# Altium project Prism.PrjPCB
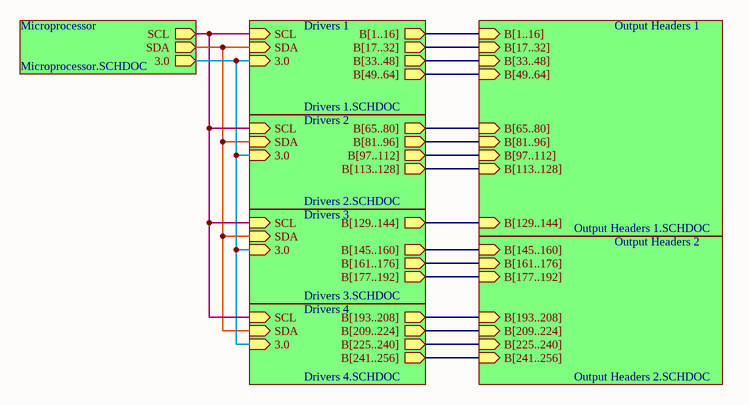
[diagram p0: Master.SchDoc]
8 sheets, 82 parts. Net scope: hierarchical (ports join the sheet entries above them; power ports are global).
Board file: Micro Board.PCBDoc
Sheets:
  Master.SchDoc
    Output Headers 2 = Output Headers 2.SchDoc
    Output Headers 1 = Output Headers 1.SchDoc
    Microprocessor = Microprocessor.SchDoc
    Drivers 1 = Drivers 1.SchDoc
    Drivers 2 = Drivers 2.SchDoc
    Drivers 3 = Drivers 3.SchDoc
    Drivers 4 = Drivers 4.SchDoc

## Sheet Master.SchDoc: Master
size A; DocumentNumber: 1; SheetNumber: 1

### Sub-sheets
Drivers 1 = Drivers 1.SCHDOC: B[1..16] (out), B[17..32] (out), B[33..48] (out), B[49..64] (out), SCL (in), SDA (in), 3.0 (in)
Drivers 2 = Drivers 2.SCHDOC: B[97..112] (out), B[113..128] (out), B[65..80] (out), B[81..96] (out), SCL (in), SDA (in), 3.0 (in)
Drivers 3 = Drivers 3.SCHDOC: B[161..176] (out), B[177..192] (out), B[129..144] (out), B[145..160] (out), SCL (in), SDA (in), 3.0 (in)
Drivers 4 = Drivers 4.SCHDOC: B[241..256] (out), B[193..208] (out), B[209..224] (out), B[225..240] (out), SCL (in), SDA (in), 3.0 (in)
Microprocessor = Microprocessor.SCHDOC: SDA (out), SCL (out), 3.0 (out)
Output Headers 1 = Output Headers 1.SCHDOC: B[1..16] (in), B[17..32] (in), B[33..48] (in), B[81..96] (in), B[65..80] (in), B[49..64] (in), B[97..112] (in), B[113..128] (in), B[129..144] (in)
Output Headers 2 = Output Headers 2.SCHDOC: B[177..192] (in), B[161..176] (in), B[145..160] (in), B[193..208] (in), B[209..224] (in), B[225..240] (in), B[241..256] (in)

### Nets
NetC1_1: sheet Microprocessor/3.0, sheet Drivers 1/3.0, sheet Drivers 2/3.0, sheet Drivers 3/3.0, sheet Drivers 4/3.0
NetR33_1: sheet Microprocessor/SDA, sheet Drivers 1/SDA, sheet Drivers 2/SDA, sheet Drivers 3/SDA, sheet Drivers 4/SDA
NetR34_1: sheet Microprocessor/SCL, sheet Drivers 1/SCL, sheet Drivers 2/SCL, sheet Drivers 3/SCL, sheet Drivers 4/SCL

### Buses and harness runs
bus sheet Drivers 1/B[1..16] = sheet Output Headers 1/B[1..16]
bus sheet Drivers 1/B[17..32] = sheet Output Headers 1/B[17..32]
bus sheet Drivers 1/B[33..48] = sheet Output Headers 1/B[33..48]
bus sheet Drivers 1/B[49..64] = sheet Output Headers 1/B[49..64]
bus sheet Drivers 2/B[65..80] = sheet Output Headers 1/B[65..80]
bus sheet Drivers 2/B[81..96] = sheet Output Headers 1/B[81..96]
bus sheet Drivers 2/B[97..112] = sheet Output Headers 1/B[97..112]
bus sheet Drivers 2/B[113..128] = sheet Output Headers 1/B[113..128]
bus sheet Drivers 3/B[129..144] = sheet Output Headers 1/B[129..144]
bus sheet Drivers 3/B[145..160] = sheet Output Headers 2/B[145..160]
bus sheet Drivers 3/B[161..176] = sheet Output Headers 2/B[161..176]
bus sheet Drivers 3/B[177..192] = sheet Output Headers 2/B[177..192]
bus sheet Drivers 4/B[193..208] = sheet Output Headers 2/B[193..208]
bus sheet Drivers 4/B[209..224] = sheet Output Headers 2/B[209..224]
bus sheet Drivers 4/B[225..240] = sheet Output Headers 2/B[225..240]
bus sheet Drivers 4/B[241..256] = sheet Output Headers 2/B[241..256]

## Sheet Output Headers 2.SchDoc: Output Header Connections 2
size A; DocumentNumber: 1; SheetNumber: 7
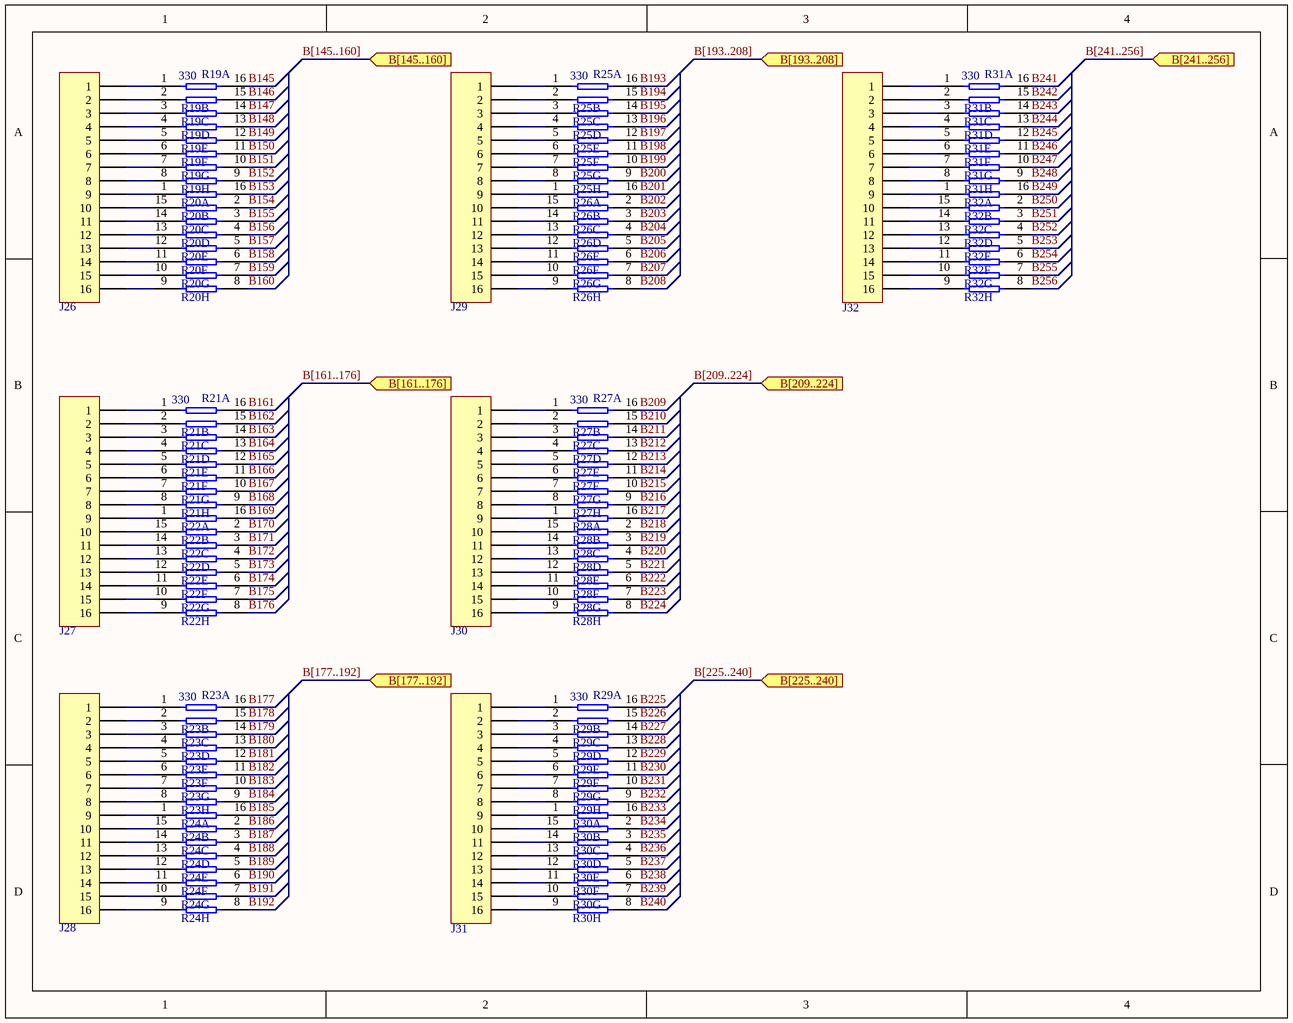
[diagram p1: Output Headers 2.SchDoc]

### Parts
J26  HDR2X8  [HDR2X8]  (value not drawn)
J27  HDR2X8  [HDR2X8]  (value not drawn)
J28  HDR2X8  [HDR2X8]  (value not drawn)
J29  HDR2X8  [HDR2X8]  (value not drawn)
J30  HDR2X8  [HDR2X8]  (value not drawn)
J31  HDR2X8  [HDR2X8]  (value not drawn)
J32  HDR2X8  [HDR2X8]  (value not drawn)
R19  330  [DIP-16]  (parts A,B,C,D,E,F,G,H of 8)
R20  330  [DIP-16]  (value not drawn)  (parts A,B,C,D,E,F,G,H of 8)
R21  330  [DIP-16]  (parts A,B,C,D,E,F,G,H of 8)
R22  330  [DIP-16]  (value not drawn)  (parts A,B,C,D,E,F,G,H of 8)
R23  330  [DIP-16]  (parts A,B,C,D,E,F,G,H of 8)
R24  330  [DIP-16]  (value not drawn)  (parts A,B,C,D,E,F,G,H of 8)
R25  330  [DIP-16]  (parts A,B,C,D,E,F,G,H of 8)
R26  330  [DIP-16]  (value not drawn)  (parts A,B,C,D,E,F,G,H of 8)
R27  330  [DIP-16]  (parts A,B,C,D,E,F,G,H of 8)
R28  330  [DIP-16]  (value not drawn)  (parts A,B,C,D,E,F,G,H of 8)
R29  330  [DIP-16]  (parts A,B,C,D,E,F,G,H of 8)
R30  330  [DIP-16]  (value not drawn)  (parts A,B,C,D,E,F,G,H of 8)
R31  330  [DIP-16]  (parts A,B,C,D,E,F,G,H of 8)
R32  330  [DIP-16]  (value not drawn)  (parts A,B,C,D,E,F,G,H of 8)

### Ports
B[145..160] (in), B[161..176] (in), B[177..192] (in), B[193..208] (in), B[209..224] (in), B[225..240] (in), B[241..256] (in)

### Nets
B145: R19.16
B146: R19.15
B147: R19.14
B148: R19.13
B149: R19.12
B150: R19.11
B151: R19.10
B152: R19.9
B153: R20.16
B154: R20.2
B155: R20.3
B156: R20.4
B157: R20.5
B158: R20.6
B159: R20.7
B160: R20.8
B161: R21.16
B162: R21.15
B163: R21.14
B164: R21.13
B165: R21.12
B166: R21.11
B167: R21.10
B168: R21.9
B169: R22.16
B170: R22.2
B171: R22.3
B172: R22.4
B173: R22.5
B174: R22.6
B175: R22.7
B176: R22.8
B177: R23.16
B178: R23.15
B179: R23.14
B180: R23.13
B181: R23.12
B182: R23.11
B183: R23.10
B184: R23.9
B185: R24.16
B186: R24.2
B187: R24.3
B188: R24.4
B189: R24.5
B190: R24.6
B191: R24.7
B192: R24.8
B193: R25.16
B194: R25.15
B195: R25.14
B196: R25.13
B197: R25.12
B198: R25.11
B199: R25.10
B200: R25.9
B201: R26.16
B202: R26.2
B203: R26.3
B204: R26.4
B205: R26.5
B206: R26.6
B207: R26.7
B208: R26.8
B209: R27.16
B210: R27.15
B211: R27.14
B212: R27.13
B213: R27.12
B214: R27.11
B215: R27.10
B216: R27.9
B217: R28.16
B218: R28.2
B219: R28.3
B220: R28.4
B221: R28.5
B222: R28.6
B223: R28.7
B224: R28.8
B225: R29.16
B226: R29.15
B227: R29.14
B228: R29.13
B229: R29.12
B230: R29.11
B231: R29.10
B232: R29.9
B233: R30.16
B234: R30.2
B235: R30.3
B236: R30.4
B237: R30.5
B238: R30.6
B239: R30.7
B240: R30.8
B241: R31.16
B242: R31.15
B243: R31.14
B244: R31.13
B245: R31.12
B246: R31.11
B247: R31.10
B248: R31.9
B249: R32.16
B250: R32.2
B251: R32.3
B252: R32.4
B253: R32.5
B254: R32.6
B255: R32.7
B256: R32.8
NetJ26_1: J26.1 R19.1
NetJ26_2: J26.2 R19.2
NetJ26_3: J26.3 R19.3
NetJ26_4: J26.4 R19.4
NetJ26_5: J26.5 R19.5
NetJ26_6: J26.6 R19.6
NetJ26_7: J26.7 R19.7
NetJ26_8: J26.8 R19.8
NetJ26_9: J26.9 R20.1
NetJ26_10: J26.10 R20.15
NetJ26_11: J26.11 R20.14
NetJ26_12: J26.12 R20.13
NetJ26_13: J26.13 R20.12
NetJ26_14: J26.14 R20.11
NetJ26_15: J26.15 R20.10
NetJ26_16: J26.16 R20.9
NetJ27_1: J27.1 R21.1
NetJ27_2: J27.2 R21.2
NetJ27_3: J27.3 R21.3
NetJ27_4: J27.4 R21.4
NetJ27_5: J27.5 R21.5
NetJ27_6: J27.6 R21.6
NetJ27_7: J27.7 R21.7
NetJ27_8: J27.8 R21.8
NetJ27_9: J27.9 R22.1
NetJ27_10: J27.10 R22.15
NetJ27_11: J27.11 R22.14
NetJ27_12: J27.12 R22.13
NetJ27_13: J27.13 R22.12
NetJ27_14: J27.14 R22.11
NetJ27_15: J27.15 R22.10
NetJ27_16: J27.16 R22.9
NetJ28_1: J28.1 R23.1
NetJ28_2: J28.2 R23.2
NetJ28_3: J28.3 R23.3
NetJ28_4: J28.4 R23.4
NetJ28_5: J28.5 R23.5
NetJ28_6: J28.6 R23.6
NetJ28_7: J28.7 R23.7
NetJ28_8: J28.8 R23.8
NetJ28_9: J28.9 R24.1
NetJ28_10: J28.10 R24.15
NetJ28_11: J28.11 R24.14
NetJ28_12: J28.12 R24.13
NetJ28_13: J28.13 R24.12
NetJ28_14: J28.14 R24.11
NetJ28_15: J28.15 R24.10
NetJ28_16: J28.16 R24.9
NetJ29_1: J29.1 R25.1
NetJ29_2: J29.2 R25.2
NetJ29_3: J29.3 R25.3
NetJ29_4: J29.4 R25.4
NetJ29_5: J29.5 R25.5
NetJ29_6: J29.6 R25.6
NetJ29_7: J29.7 R25.7
NetJ29_8: J29.8 R25.8
NetJ29_9: J29.9 R26.1
NetJ29_10: J29.10 R26.15
NetJ29_11: J29.11 R26.14
NetJ29_12: J29.12 R26.13
NetJ29_13: J29.13 R26.12
NetJ29_14: J29.14 R26.11
NetJ29_15: J29.15 R26.10
NetJ29_16: J29.16 R26.9
NetJ30_1: J30.1 R27.1
NetJ30_2: J30.2 R27.2
NetJ30_3: J30.3 R27.3
NetJ30_4: J30.4 R27.4
NetJ30_5: J30.5 R27.5
NetJ30_6: J30.6 R27.6
NetJ30_7: J30.7 R27.7
NetJ30_8: J30.8 R27.8
NetJ30_9: J30.9 R28.1
NetJ30_10: J30.10 R28.15
NetJ30_11: J30.11 R28.14
NetJ30_12: J30.12 R28.13
NetJ30_13: J30.13 R28.12
NetJ30_14: J30.14 R28.11
NetJ30_15: J30.15 R28.10
NetJ30_16: J30.16 R28.9
NetJ31_1: J31.1 R29.1
NetJ31_2: J31.2 R29.2
NetJ31_3: J31.3 R29.3
NetJ31_4: J31.4 R29.4
NetJ31_5: J31.5 R29.5
NetJ31_6: J31.6 R29.6
NetJ31_7: J31.7 R29.7
NetJ31_8: J31.8 R29.8
NetJ31_9: J31.9 R30.1
NetJ31_10: J31.10 R30.15
NetJ31_11: J31.11 R30.14
NetJ31_12: J31.12 R30.13
NetJ31_13: J31.13 R30.12
NetJ31_14: J31.14 R30.11
NetJ31_15: J31.15 R30.10
NetJ31_16: J31.16 R30.9
NetJ32_1: J32.1 R31.1
NetJ32_2: J32.2 R31.2
NetJ32_3: J32.3 R31.3
NetJ32_4: J32.4 R31.4
NetJ32_5: J32.5 R31.5
NetJ32_6: J32.6 R31.6
NetJ32_7: J32.7 R31.7
NetJ32_8: J32.8 R31.8
NetJ32_9: J32.9 R32.1
NetJ32_10: J32.10 R32.15
NetJ32_11: J32.11 R32.14
NetJ32_12: J32.12 R32.13
NetJ32_13: J32.13 R32.12
NetJ32_14: J32.14 R32.11
NetJ32_15: J32.15 R32.10
NetJ32_16: J32.16 R32.9

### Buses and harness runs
bus B[145..160] = port B[145..160]
bus B[161..176] = port B[161..176]
bus B[177..192] = port B[177..192]
bus B[193..208] = port B[193..208]
bus B[209..224] = port B[209..224]
bus B[225..240] = port B[225..240]
bus B[241..256] = port B[241..256]

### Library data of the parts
J26-J32 = MHDR1X16: Header, 16-Pin; Manufacturer: Generic Components; Class I: Connector
R19-R32 = Res Pack2: Resistor Array - Parts; Manufacturer: Generic Components; Class I: Passive; Value: 1K

## Sheet Output Headers 1.SchDoc: Output Headers
size A; DocumentNumber: 1; SheetNumber: 6
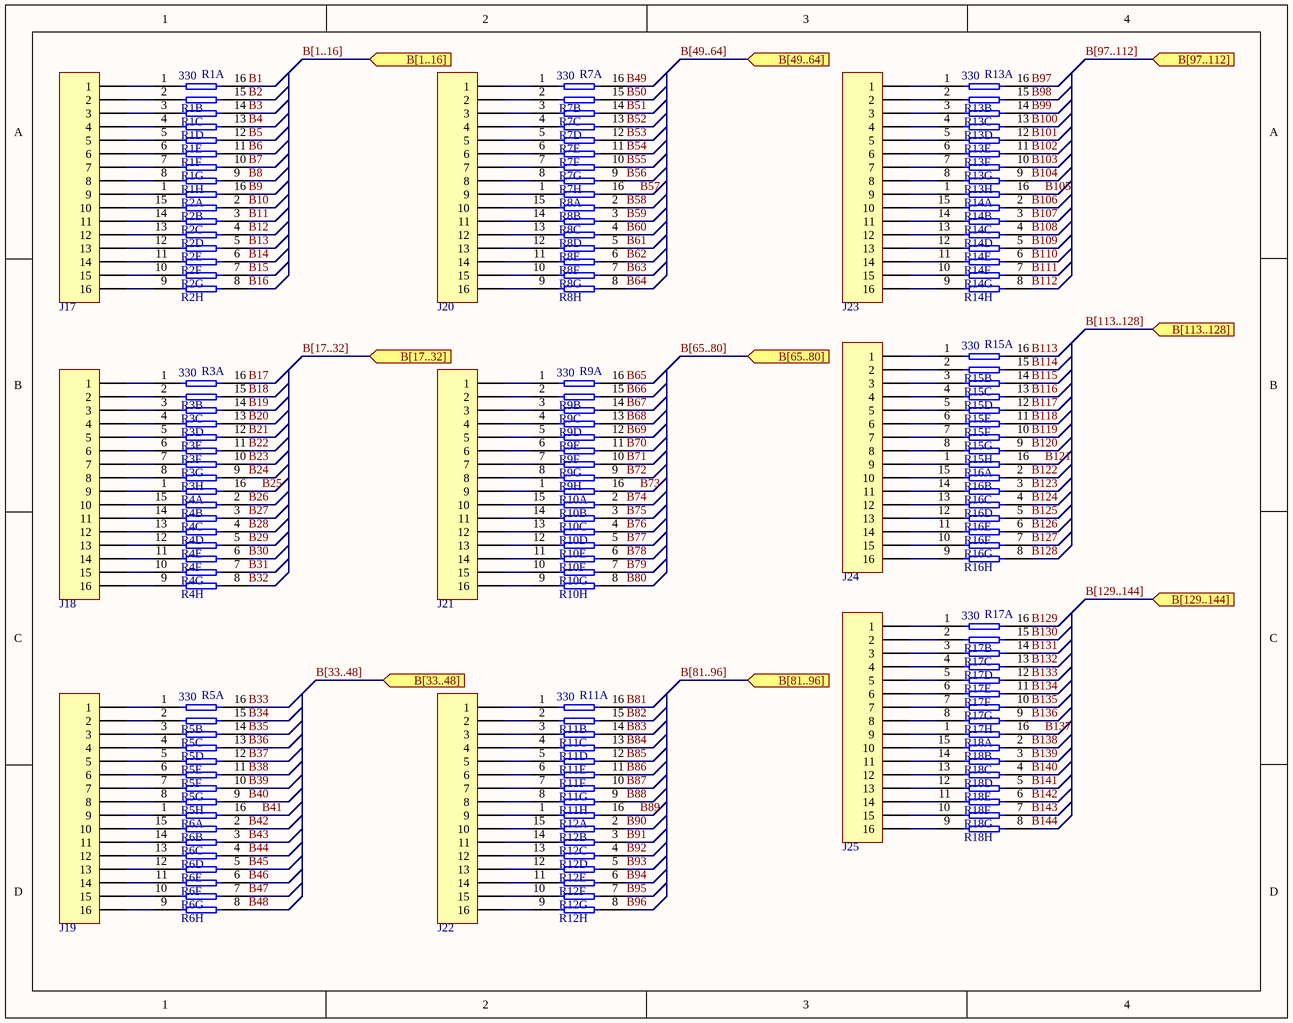
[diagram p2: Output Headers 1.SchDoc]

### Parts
J17  HDR2X8  [HDR2X8]  (value not drawn)
J18  HDR2X8  [HDR2X8]  (value not drawn)
J19  HDR2X8  [HDR2X8]  (value not drawn)
J20  HDR2X8  [HDR2X8]  (value not drawn)
J21  HDR2X8  [HDR2X8]  (value not drawn)
J22  HDR2X8  [HDR2X8]  (value not drawn)
J23  HDR2X8  [HDR2X8]  (value not drawn)
J24  HDR2X8  [HDR2X8]  (value not drawn)
J25  HDR2X8  [HDR2X8]  (value not drawn)
R1  330  [DIP-16]  (parts A,B,C,D,E,F,G,H of 8)
R2  330  [DIP-16]  (value not drawn)  (parts A,B,C,D,E,F,G,H of 8)
R3  330  [DIP-16]  (parts A,B,C,D,E,F,G,H of 8)
R4  330  [DIP-16]  (value not drawn)  (parts A,B,C,D,E,F,G,H of 8)
R5  330  [DIP-16]  (parts A,B,C,D,E,F,G,H of 8)
R6  330  [DIP-16]  (value not drawn)  (parts A,B,C,D,E,F,G,H of 8)
R7  330  [DIP-16]  (parts A,B,C,D,E,F,G,H of 8)
R8  330  [DIP-16]  (value not drawn)  (parts A,B,C,D,E,F,G,H of 8)
R9  330  [DIP-16]  (parts A,B,C,D,E,F,G,H of 8)
R10  330  [DIP-16]  (value not drawn)  (parts A,B,C,D,E,F,G,H of 8)
R11  330  [DIP-16]  (parts A,B,C,D,E,F,G,H of 8)
R12  330  [DIP-16]  (value not drawn)  (parts A,B,C,D,E,F,G,H of 8)
R13  330  [DIP-16]  (parts A,B,C,D,E,F,G,H of 8)
R14  330  [DIP-16]  (value not drawn)  (parts A,B,C,D,E,F,G,H of 8)
R15  330  [DIP-16]  (parts A,B,C,D,E,F,G,H of 8)
R16  330  [DIP-16]  (value not drawn)  (parts A,B,C,D,E,F,G,H of 8)
R17  330  [DIP-16]  (parts A,B,C,D,E,F,G,H of 8)
R18  330  [DIP-16]  (value not drawn)  (parts A,B,C,D,E,F,G,H of 8)

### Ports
B[1..16] (in), B[17..32] (in), B[33..48] (in), B[49..64] (in), B[65..80] (in), B[81..96] (in), B[97..112] (in), B[113..128] (in), B[129..144] (in)

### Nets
B1: R1.16
B2: R1.15
B3: R1.14
B4: R1.13
B5: R1.12
B6: R1.11
B7: R1.10
B8: R1.9
B9: R2.16
B10: R2.2
B11: R2.3
B12: R2.4
B13: R2.5
B14: R2.6
B15: R2.7
B16: R2.8
B17: R3.16
B18: R3.15
B19: R3.14
B20: R3.13
B21: R3.12
B22: R3.11
B23: R3.10
B24: R3.9
B25: R4.16
B26: R4.2
B27: R4.3
B28: R4.4
B29: R4.5
B30: R4.6
B31: R4.7
B32: R4.8
B33: R5.16
B34: R5.15
B35: R5.14
B36: R5.13
B37: R5.12
B38: R5.11
B39: R5.10
B40: R5.9
B41: R6.16
B42: R6.2
B43: R6.3
B44: R6.4
B45: R6.5
B46: R6.6
B47: R6.7
B48: R6.8
B49: R7.16
B50: R7.15
B51: R7.14
B52: R7.13
B53: R7.12
B54: R7.11
B55: R7.10
B56: R7.9
B57: R8.16
B58: R8.2
B59: R8.3
B60: R8.4
B61: R8.5
B62: R8.6
B63: R8.7
B64: R8.8
B65: R9.16
B66: R9.15
B67: R9.14
B68: R9.13
B69: R9.12
B70: R9.11
B71: R9.10
B72: R9.9
B73: R10.16
B74: R10.2
B75: R10.3
B76: R10.4
B77: R10.5
B78: R10.6
B79: R10.7
B80: R10.8
B81: R11.16
B82: R11.15
B83: R11.14
B84: R11.13
B85: R11.12
B86: R11.11
B87: R11.10
B88: R11.9
B89: R12.16
B90: R12.2
B91: R12.3
B92: R12.4
B93: R12.5
B94: R12.6
B95: R12.7
B96: R12.8
B97: R13.16
B98: R13.15
B99: R13.14
B100: R13.13
B101: R13.12
B102: R13.11
B103: R13.10
B104: R13.9
B105: R14.16
B106: R14.2
B107: R14.3
B108: R14.4
B109: R14.5
B110: R14.6
B111: R14.7
B112: R14.8
B113: R15.16
B114: R15.15
B115: R15.14
B116: R15.13
B117: R15.12
B118: R15.11
B119: R15.10
B120: R15.9
B121: R16.16
B122: R16.2
B123: R16.3
B124: R16.4
B125: R16.5
B126: R16.6
B127: R16.7
B128: R16.8
B129: R17.16
B130: R17.15
B131: R17.14
B132: R17.13
B133: R17.12
B134: R17.11
B135: R17.10
B136: R17.9
B137: R18.16
B138: R18.2
B139: R18.3
B140: R18.4
B141: R18.5
B142: R18.6
B143: R18.7
B144: R18.8
NetJ17_1: J17.1 R1.1
NetJ17_2: J17.2 R1.2
NetJ17_3: J17.3 R1.3
NetJ17_4: J17.4 R1.4
NetJ17_5: J17.5 R1.5
NetJ17_6: J17.6 R1.6
NetJ17_7: J17.7 R1.7
NetJ17_8: J17.8 R1.8
NetJ17_9: J17.9 R2.1
NetJ17_10: J17.10 R2.15
NetJ17_11: J17.11 R2.14
NetJ17_12: J17.12 R2.13
NetJ17_13: J17.13 R2.12
NetJ17_14: J17.14 R2.11
NetJ17_15: J17.15 R2.10
NetJ17_16: J17.16 R2.9
NetJ18_1: J18.1 R3.1
NetJ18_2: J18.2 R3.2
NetJ18_3: J18.3 R3.3
NetJ18_4: J18.4 R3.4
NetJ18_5: J18.5 R3.5
NetJ18_6: J18.6 R3.6
NetJ18_7: J18.7 R3.7
NetJ18_8: J18.8 R3.8
NetJ18_9: J18.9 R4.1
NetJ18_10: J18.10 R4.15
NetJ18_11: J18.11 R4.14
NetJ18_12: J18.12 R4.13
NetJ18_13: J18.13 R4.12
NetJ18_14: J18.14 R4.11
NetJ18_15: J18.15 R4.10
NetJ18_16: J18.16 R4.9
NetJ19_1: J19.1 R5.1
NetJ19_2: J19.2 R5.2
NetJ19_3: J19.3 R5.3
NetJ19_4: J19.4 R5.4
NetJ19_5: J19.5 R5.5
NetJ19_6: J19.6 R5.6
NetJ19_7: J19.7 R5.7
NetJ19_8: J19.8 R5.8
NetJ19_9: J19.9 R6.1
NetJ19_10: J19.10 R6.15
NetJ19_11: J19.11 R6.14
NetJ19_12: J19.12 R6.13
NetJ19_13: J19.13 R6.12
NetJ19_14: J19.14 R6.11
NetJ19_15: J19.15 R6.10
NetJ19_16: J19.16 R6.9
NetJ20_1: J20.1 R7.1
NetJ20_2: J20.2 R7.2
NetJ20_3: J20.3 R7.3
NetJ20_4: J20.4 R7.4
NetJ20_5: J20.5 R7.5
NetJ20_6: J20.6 R7.6
NetJ20_7: J20.7 R7.7
NetJ20_8: J20.8 R7.8
NetJ20_9: J20.9 R8.1
NetJ20_10: J20.10 R8.15
NetJ20_11: J20.11 R8.14
NetJ20_12: J20.12 R8.13
NetJ20_13: J20.13 R8.12
NetJ20_14: J20.14 R8.11
NetJ20_15: J20.15 R8.10
NetJ20_16: J20.16 R8.9
NetJ21_1: J21.1 R9.1
NetJ21_2: J21.2 R9.2
NetJ21_3: J21.3 R9.3
NetJ21_4: J21.4 R9.4
NetJ21_5: J21.5 R9.5
NetJ21_6: J21.6 R9.6
NetJ21_7: J21.7 R9.7
NetJ21_8: J21.8 R9.8
NetJ21_9: J21.9 R10.1
NetJ21_10: J21.10 R10.15
NetJ21_11: J21.11 R10.14
NetJ21_12: J21.12 R10.13
NetJ21_13: J21.13 R10.12
NetJ21_14: J21.14 R10.11
NetJ21_15: J21.15 R10.10
NetJ21_16: J21.16 R10.9
NetJ22_1: J22.1 R11.1
NetJ22_2: J22.2 R11.2
NetJ22_3: J22.3 R11.3
NetJ22_4: J22.4 R11.4
NetJ22_5: J22.5 R11.5
NetJ22_6: J22.6 R11.6
NetJ22_7: J22.7 R11.7
NetJ22_8: J22.8 R11.8
NetJ22_9: J22.9 R12.1
NetJ22_10: J22.10 R12.15
NetJ22_11: J22.11 R12.14
NetJ22_12: J22.12 R12.13
NetJ22_13: J22.13 R12.12
NetJ22_14: J22.14 R12.11
NetJ22_15: J22.15 R12.10
NetJ22_16: J22.16 R12.9
NetJ23_1: J23.1 R13.1
NetJ23_2: J23.2 R13.2
NetJ23_3: J23.3 R13.3
NetJ23_4: J23.4 R13.4
NetJ23_5: J23.5 R13.5
NetJ23_6: J23.6 R13.6
NetJ23_7: J23.7 R13.7
NetJ23_8: J23.8 R13.8
NetJ23_9: J23.9 R14.1
NetJ23_10: J23.10 R14.15
NetJ23_11: J23.11 R14.14
NetJ23_12: J23.12 R14.13
NetJ23_13: J23.13 R14.12
NetJ23_14: J23.14 R14.11
NetJ23_15: J23.15 R14.10
NetJ23_16: J23.16 R14.9
NetJ24_1: J24.1 R15.1
NetJ24_2: J24.2 R15.2
NetJ24_3: J24.3 R15.3
NetJ24_4: J24.4 R15.4
NetJ24_5: J24.5 R15.5
NetJ24_6: J24.6 R15.6
NetJ24_7: J24.7 R15.7
NetJ24_8: J24.8 R15.8
NetJ24_9: J24.9 R16.1
NetJ24_10: J24.10 R16.15
NetJ24_11: J24.11 R16.14
NetJ24_12: J24.12 R16.13
NetJ24_13: J24.13 R16.12
NetJ24_14: J24.14 R16.11
NetJ24_15: J24.15 R16.10
NetJ24_16: J24.16 R16.9
NetJ25_1: J25.1 R17.1
NetJ25_2: J25.2 R17.2
NetJ25_3: J25.3 R17.3
NetJ25_4: J25.4 R17.4
NetJ25_5: J25.5 R17.5
NetJ25_6: J25.6 R17.6
NetJ25_7: J25.7 R17.7
NetJ25_8: J25.8 R17.8
NetJ25_9: J25.9 R18.1
NetJ25_10: J25.10 R18.15
NetJ25_11: J25.11 R18.14
NetJ25_12: J25.12 R18.13
NetJ25_13: J25.13 R18.12
NetJ25_14: J25.14 R18.11
NetJ25_15: J25.15 R18.10
NetJ25_16: J25.16 R18.9

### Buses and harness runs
bus B[1..16] = port B[1..16]
bus B[17..32] = port B[17..32]
bus B[33..48] = port B[33..48]
bus B[49..64] = port B[49..64]
bus B[65..80] = port B[65..80]
bus B[81..96] = port B[81..96]
bus B[97..112] = port B[97..112]
bus B[113..128] = port B[113..128]
bus B[129..144] = port B[129..144]

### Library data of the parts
J17-J25 = MHDR1X16: as J26 on sheet Output Headers 2
R1-R18 = Res Pack2: as R19 on sheet Output Headers 2

## Sheet Microprocessor.SchDoc: Microprocessor
size A; DocumentNumber: 1; SheetNumber: 12
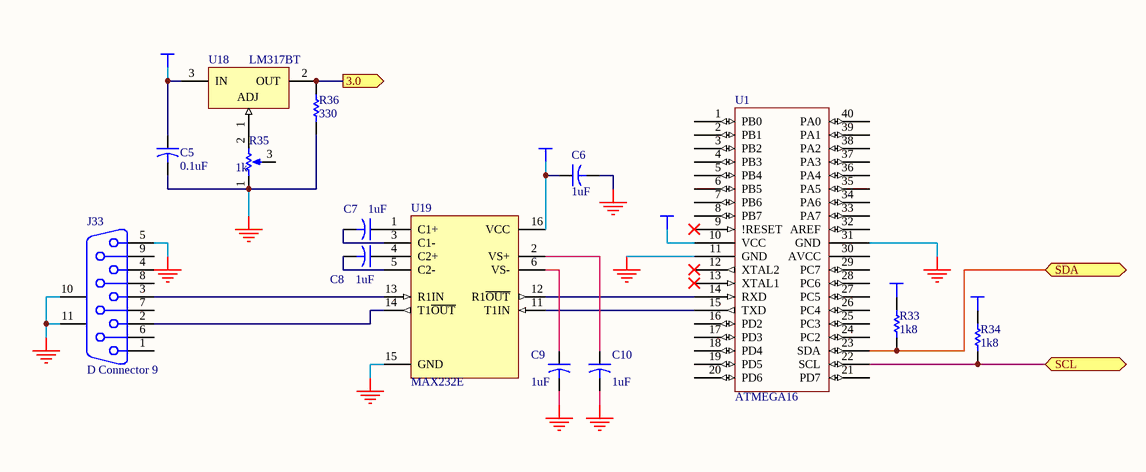
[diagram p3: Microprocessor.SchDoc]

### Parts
C5  0.1uF  [CAPR5-4X5]
C6  1uF  [CAPR5-4X5]
C7  1uF  [CAPR5-4X5]
C8  1uF  [CAPR5-4X5]
C9  1uF  [CAPR5-4X5]
C10  1uF  [CAPR5-4X5]
J33  D Connector 9  [DSUB1.385-2H9]
R33  1k8  [AXIAL-0.3]
R34  1k8  [AXIAL-0.3]
R35  1k  [VR5]
R36  330  [AXIAL-0.3]
U1  ATMEGA16  [DIP-40]
U18  LM317BT  [SFM-T3/X1.6V]
U19  MAX232E  [DIP-16]

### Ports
3.0, SCL (bidir), SDA (bidir)

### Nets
+5: C5.1 C6.1 R33.2 R34.2 U1.10(VCC) U18.3(IN) U19.16(VCC)
GND: C5.2 C6.2 C9.2 C10.2 J33.5 J33.10(MH1) J33.11(MH2) R35.1(TOP) R36.1 U1.11(GND) U1.31(GND) U19.15(GND)
NetC1_1: R36.2 U18.2(OUT) ; port 3.0
NetC7_1: C7.1 U19.1(C1+)
NetC7_2: C7.2 U19.3(C1-)
NetC8_1: C8.1 U19.4(C2+)
NetC8_2: C8.2 U19.5(C2-)
NetC9_1: C9.1 U19.6(VS-)
NetC10_1: C10.1 U19.2(VS+)
NetJ33_2: J33.2 U19.14(T1~{OUT})
NetJ33_3: J33.3 U19.13(R1IN)
NetR33_1: R33.1 U1.23(SDA) ; port SDA
NetR34_1: R34.1 U1.22(SCL) ; port SCL
NetR35_2: R35.2(BOT) U18.1(ADJ)
NetU1_14: U1.14(RXD) U19.12(R1~{OUT})
NetU1_15: U1.15(TXD) U19.11(T1IN)

Not connected (* = marked no-connect by the designer): J33 1 4 6 7 8 9; R35 3(TAP); U1 1(PB0) 2(PB1) 3(PB2) 4(PB3) 5(PB4) 6(PB5) 7(PB6) 8(PB7) 9(!RESET)* 12(XTAL2)* 13(XTAL1)* 16(PD2) 17(PD3) 18(PD4) 19(PD5) 20(PD6) 21(PD7) 24(PC2) 25(PC3) 26(PC4) 27(PC5) 28(PC6) 29(PC7) 30(AVCC) 32(AREF) 33(PA7) 34(PA6) 35(PA5) 36(PA4) 37(PA3) 38(PA2) 39(PA1) 40(PA0); U19 7(T2~{OUT}) 8(R2IN) 9(R2~{OUT}) 10(T2IN)

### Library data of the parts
C5-C10 = Cap2: Capacitor; Manufacturer: Generic Components; Class I: Passive; Value: 100pF
J33 = D Connector 9: Receptacle Assembly, 9 Position, Right Angle; Manufacturer: Generic Components; Package Information: Latest Revision: O; Positions: 9
R33 R34 R36 = Res1: Resistor; Manufacturer: Generic Components; Class I: Passive; Value: 1K
R35 = RPot1: Potentiometer; Manufacturer: Generic Components; Class I: Passive; Set Position: 0.5
U18 = LM317BT: 3-Terminal Adjustable Positive Voltage Regulator; Manufacturer: Motorola; Class I: Power Management; Note: Heatsink surface connected to pin 2.
U19 = MAX232N: Dual EIA-232 Driver/Receiver; Manufacturer: Texas Instruments; Class I: Interface; Class II: Line Transceiver; Note: Receivers have typical hysteresis of 0.5V

## Sheet Drivers 1.SchDoc: LED Driver Connections 1
size A; DocumentNumber: 1; SheetNumber: 8
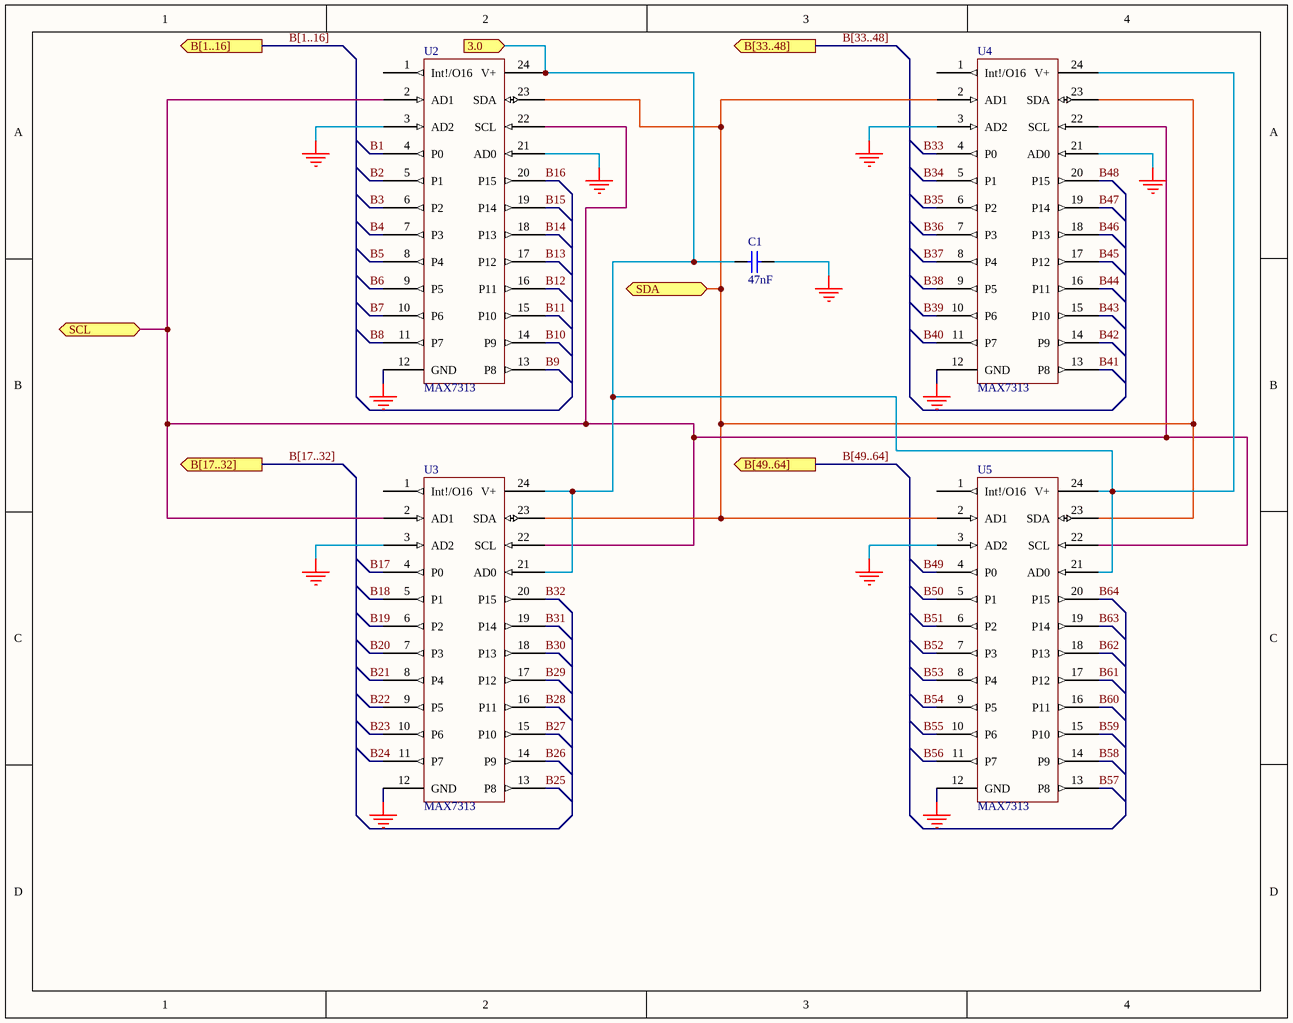
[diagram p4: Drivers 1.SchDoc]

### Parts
C1  47nF  [LED]
U2  MAX7313  [SSO-G24/C6.8]
U3  MAX7313  [SSO-G24/C6.8]
U4  MAX7313  [SSO-G24/C6.8]
U5  MAX7313  [SSO-G24/C6.8]

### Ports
3.0, B[1..16] (out), B[17..32] (out), B[33..48] (out), B[49..64] (out), SCL (bidir), SDA (bidir)

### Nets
GND: C1.2 U2.3(AD2) U2.12(GND) U2.21(AD0) U3.3(AD2) U3.12(GND) U4.3(AD2) U4.12(GND) U4.21(AD0) U5.3(AD2) U5.12(GND)
B1: U2.4(P0)
B2: U2.5(P1)
B3: U2.6(P2)
B4: U2.7(P3)
B5: U2.8(P4)
B6: U2.9(P5)
B7: U2.10(P6)
B8: U2.11(P7)
B9: U2.13(P8)
B10: U2.14(P9)
B11: U2.15(P10)
B12: U2.16(P11)
B13: U2.17(P12)
B14: U2.18(P13)
B15: U2.19(P14)
B16: U2.20(P15)
B17: U3.4(P0)
B18: U3.5(P1)
B19: U3.6(P2)
B20: U3.7(P3)
B21: U3.8(P4)
B22: U3.9(P5)
B23: U3.10(P6)
B24: U3.11(P7)
B25: U3.13(P8)
B26: U3.14(P9)
B27: U3.15(P10)
B28: U3.16(P11)
B29: U3.17(P12)
B30: U3.18(P13)
B31: U3.19(P14)
B32: U3.20(P15)
B33: U4.4(P0)
B34: U4.5(P1)
B35: U4.6(P2)
B36: U4.7(P3)
B37: U4.8(P4)
B38: U4.9(P5)
B39: U4.10(P6)
B40: U4.11(P7)
B41: U4.13(P8)
B42: U4.14(P9)
B43: U4.15(P10)
B44: U4.16(P11)
B45: U4.17(P12)
B46: U4.18(P13)
B47: U4.19(P14)
B48: U4.20(P15)
B49: U5.4(P0)
B50: U5.5(P1)
B51: U5.6(P2)
B52: U5.7(P3)
B53: U5.8(P4)
B54: U5.9(P5)
B55: U5.10(P6)
B56: U5.11(P7)
B57: U5.13(P8)
B58: U5.14(P9)
B59: U5.15(P10)
B60: U5.16(P11)
B61: U5.17(P12)
B62: U5.18(P13)
B63: U5.19(P14)
B64: U5.20(P15)
NetC1_1: C1.1 U2.24(V+) U3.21(AD0) U3.24(V+) U4.24(V+) U5.21(AD0) U5.24(V+) ; port 3.0
NetR33_1: U2.23(SDA) U3.23(SDA) U4.2(AD1) U4.23(SDA) U5.2(AD1) U5.23(SDA) ; port SDA
NetR34_1: U2.2(AD1) U2.22(SCL) U3.2(AD1) U3.22(SCL) U4.22(SCL) U5.22(SCL) ; port SCL

Not connected (* = marked no-connect by the designer): U2 1(Int!/O16); U3 1(Int!/O16); U4 1(Int!/O16); U5 1(Int!/O16)

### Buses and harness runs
bus B[1..16] = port B[1..16]
bus B[17..32] = port B[17..32]
bus B[33..48] = port B[33..48]
bus B[49..64] = port B[49..64]

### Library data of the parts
C1 = Cap: Capacitor; Manufacturer: Generic Components; Class I: Passive; Value: 100pF
U2-U5 = LED DRIVER

## Sheet Drivers 2.SchDoc: LED Driver Connections 2
size A; DocumentNumber: 1; SheetNumber: 9
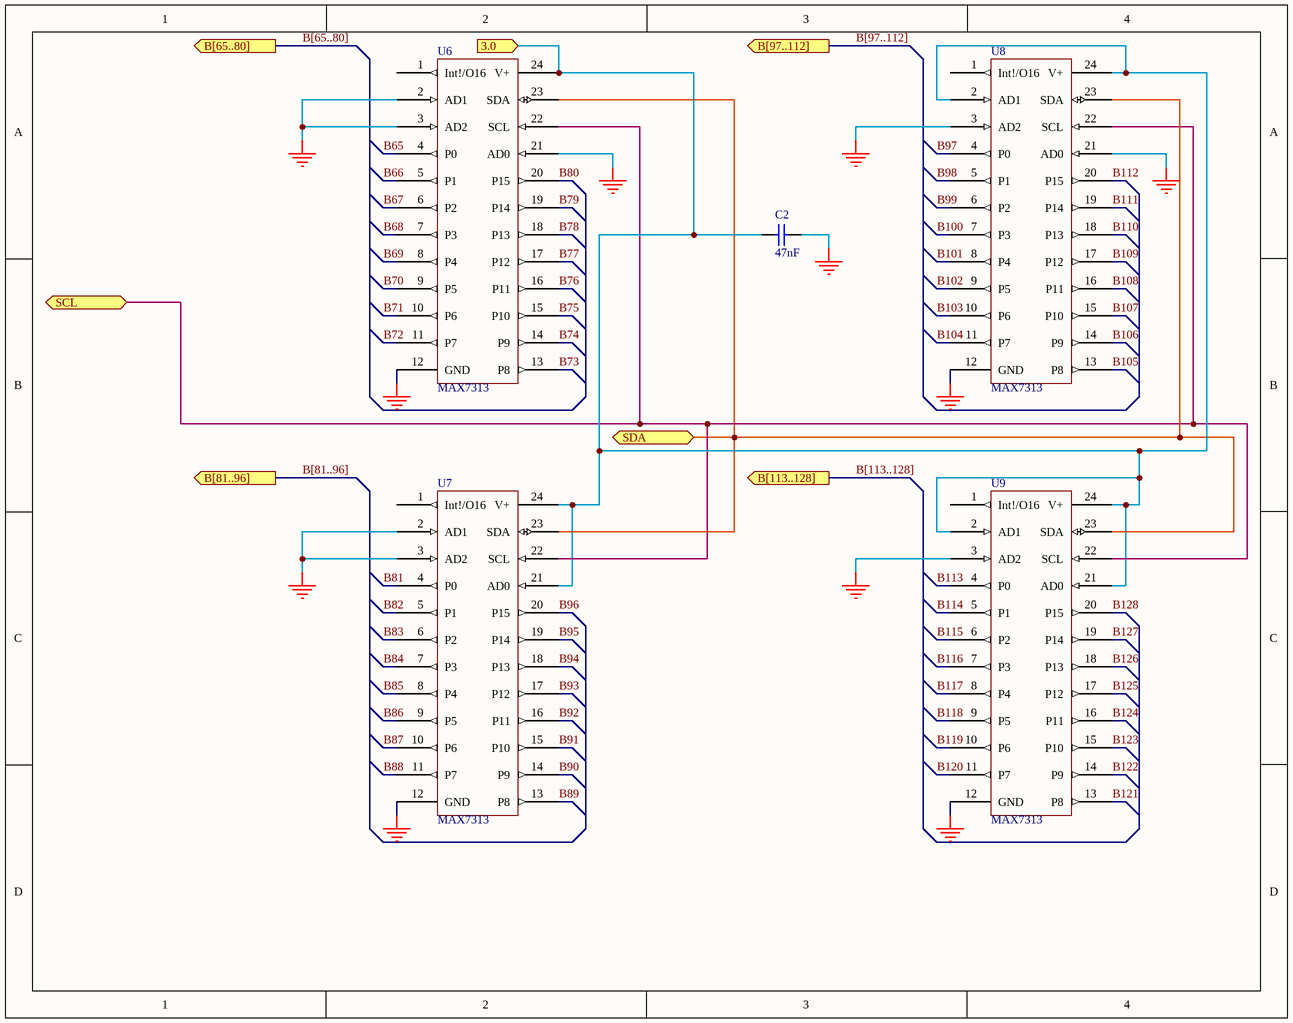
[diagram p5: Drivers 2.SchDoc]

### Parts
C2  47nF  [LED]
U6  MAX7313  [SSO-G24/C6.8]
U7  MAX7313  [SSO-G24/C6.8]
U8  MAX7313  [SSO-G24/C6.8]
U9  MAX7313  [SSO-G24/C6.8]

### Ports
3.0, B[65..80] (out), B[81..96] (out), B[97..112] (out), B[113..128] (out), SCL (bidir), SDA (bidir)

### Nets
GND: C2.2 U6.2(AD1) U6.3(AD2) U6.12(GND) U6.21(AD0) U7.2(AD1) U7.3(AD2) U7.12(GND) U8.3(AD2) U8.12(GND) U8.21(AD0) U9.3(AD2) U9.12(GND)
B65: U6.4(P0)
B66: U6.5(P1)
B67: U6.6(P2)
B68: U6.7(P3)
B69: U6.8(P4)
B70: U6.9(P5)
B71: U6.10(P6)
B72: U6.11(P7)
B73: U6.13(P8)
B74: U6.14(P9)
B75: U6.15(P10)
B76: U6.16(P11)
B77: U6.17(P12)
B78: U6.18(P13)
B79: U6.19(P14)
B80: U6.20(P15)
B81: U7.4(P0)
B82: U7.5(P1)
B83: U7.6(P2)
B84: U7.7(P3)
B85: U7.8(P4)
B86: U7.9(P5)
B87: U7.10(P6)
B88: U7.11(P7)
B89: U7.13(P8)
B90: U7.14(P9)
B91: U7.15(P10)
B92: U7.16(P11)
B93: U7.17(P12)
B94: U7.18(P13)
B95: U7.19(P14)
B96: U7.20(P15)
B97: U8.4(P0)
B98: U8.5(P1)
B99: U8.6(P2)
B100: U8.7(P3)
B101: U8.8(P4)
B102: U8.9(P5)
B103: U8.10(P6)
B104: U8.11(P7)
B105: U8.13(P8)
B106: U8.14(P9)
B107: U8.15(P10)
B108: U8.16(P11)
B109: U8.17(P12)
B110: U8.18(P13)
B111: U8.19(P14)
B112: U8.20(P15)
B113: U9.4(P0)
B114: U9.5(P1)
B115: U9.6(P2)
B116: U9.7(P3)
B117: U9.8(P4)
B118: U9.9(P5)
B119: U9.10(P6)
B120: U9.11(P7)
B121: U9.13(P8)
B122: U9.14(P9)
B123: U9.15(P10)
B124: U9.16(P11)
B125: U9.17(P12)
B126: U9.18(P13)
B127: U9.19(P14)
B128: U9.20(P15)
NetC1_1: C2.1 U6.24(V+) U7.21(AD0) U7.24(V+) U8.2(AD1) U8.24(V+) U9.2(AD1) U9.21(AD0) U9.24(V+) ; port 3.0
NetR33_1: U6.23(SDA) U7.23(SDA) U8.23(SDA) U9.23(SDA) ; port SDA
NetR34_1: U6.22(SCL) U7.22(SCL) U8.22(SCL) U9.22(SCL) ; port SCL

Not connected (* = marked no-connect by the designer): U6 1(Int!/O16); U7 1(Int!/O16); U8 1(Int!/O16); U9 1(Int!/O16)

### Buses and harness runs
bus B[65..80] = port B[65..80]
bus B[81..96] = port B[81..96]
bus B[97..112] = port B[97..112]
bus B[113..128] = port B[113..128]

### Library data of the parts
C2 = Cap: as C1 on sheet Drivers 1
U6-U9 = LED DRIVER

## Sheet Drivers 3.SchDoc: LED Driver Connections 3
size A; DocumentNumber: 1; SheetNumber: 10
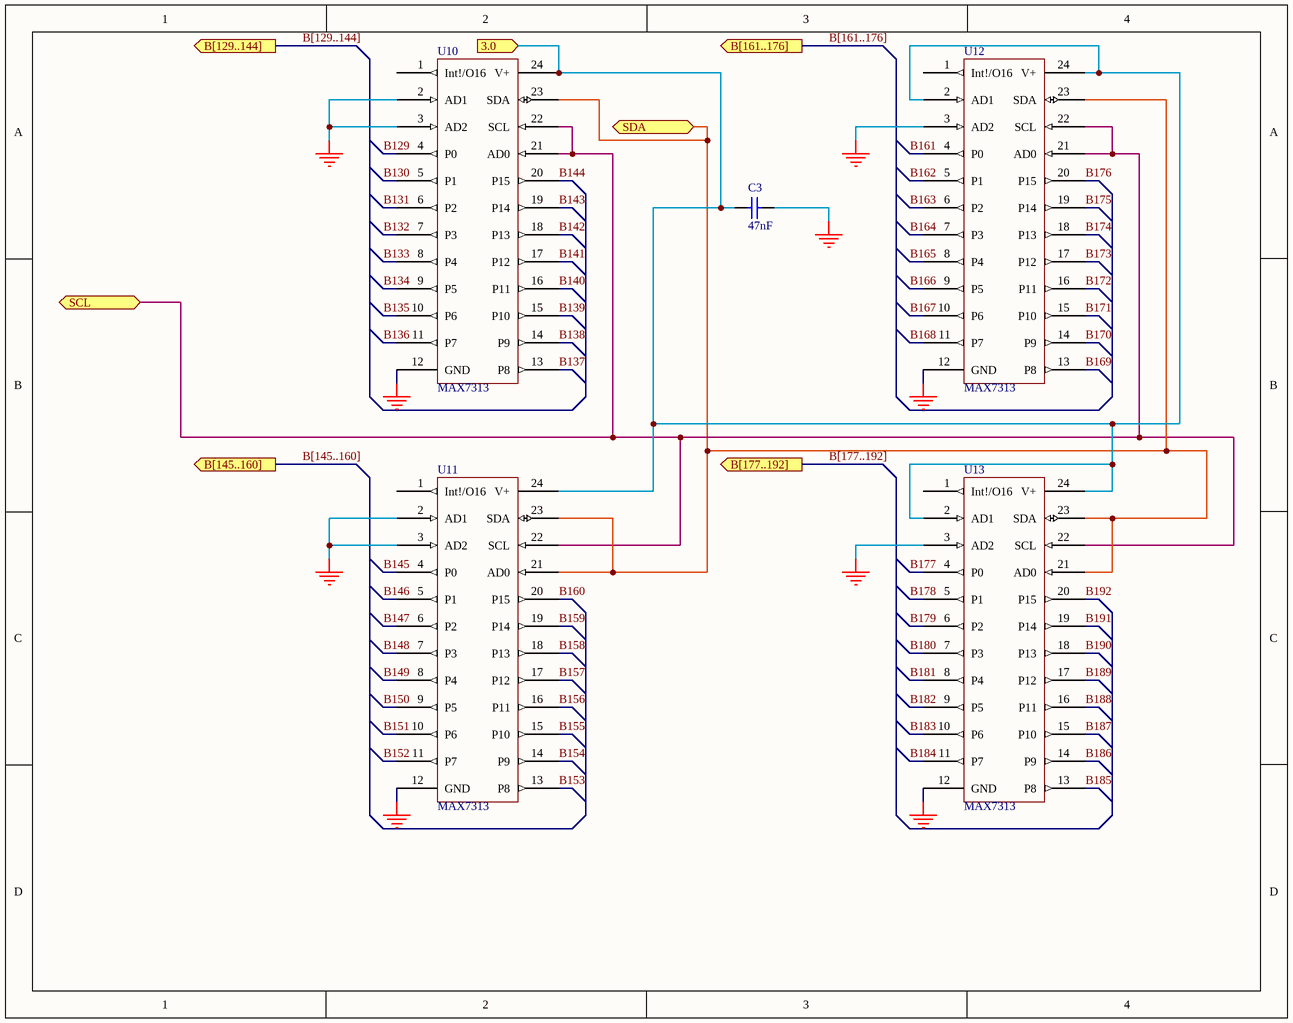
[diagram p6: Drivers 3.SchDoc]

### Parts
C3  47nF  [LED]
U10  MAX7313  [SSO-G24/C6.8]
U11  MAX7313  [SSO-G24/C6.8]
U12  MAX7313  [SSO-G24/C6.8]
U13  MAX7313  [SSO-G24/C6.8]

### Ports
3.0, B[129..144] (out), B[145..160] (out), B[161..176] (out), B[177..192] (out), SCL (bidir), SDA (bidir)

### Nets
GND: C3.2 U10.2(AD1) U10.3(AD2) U10.12(GND) U11.2(AD1) U11.3(AD2) U11.12(GND) U12.3(AD2) U12.12(GND) U13.3(AD2) U13.12(GND)
B129: U10.4(P0)
B130: U10.5(P1)
B131: U10.6(P2)
B132: U10.7(P3)
B133: U10.8(P4)
B134: U10.9(P5)
B135: U10.10(P6)
B136: U10.11(P7)
B137: U10.13(P8)
B138: U10.14(P9)
B139: U10.15(P10)
B140: U10.16(P11)
B141: U10.17(P12)
B142: U10.18(P13)
B143: U10.19(P14)
B144: U10.20(P15)
B145: U11.4(P0)
B146: U11.5(P1)
B147: U11.6(P2)
B148: U11.7(P3)
B149: U11.8(P4)
B150: U11.9(P5)
B151: U11.10(P6)
B152: U11.11(P7)
B153: U11.13(P8)
B154: U11.14(P9)
B155: U11.15(P10)
B156: U11.16(P11)
B157: U11.17(P12)
B158: U11.18(P13)
B159: U11.19(P14)
B160: U11.20(P15)
B161: U12.4(P0)
B162: U12.5(P1)
B163: U12.6(P2)
B164: U12.7(P3)
B165: U12.8(P4)
B166: U12.9(P5)
B167: U12.10(P6)
B168: U12.11(P7)
B169: U12.13(P8)
B170: U12.14(P9)
B171: U12.15(P10)
B172: U12.16(P11)
B173: U12.17(P12)
B174: U12.18(P13)
B175: U12.19(P14)
B176: U12.20(P15)
B177: U13.4(P0)
B178: U13.5(P1)
B179: U13.6(P2)
B180: U13.7(P3)
B181: U13.8(P4)
B182: U13.9(P5)
B183: U13.10(P6)
B184: U13.11(P7)
B185: U13.13(P8)
B186: U13.14(P9)
B187: U13.15(P10)
B188: U13.16(P11)
B189: U13.17(P12)
B190: U13.18(P13)
B191: U13.19(P14)
B192: U13.20(P15)
NetC1_1: C3.1 U10.24(V+) U11.24(V+) U12.2(AD1) U12.24(V+) U13.2(AD1) U13.24(V+) ; port 3.0
NetR33_1: U10.23(SDA) U11.21(AD0) U11.23(SDA) U12.23(SDA) U13.21(AD0) U13.23(SDA) ; port SDA
NetR34_1: U10.21(AD0) U10.22(SCL) U11.22(SCL) U12.21(AD0) U12.22(SCL) U13.22(SCL) ; port SCL

Not connected (* = marked no-connect by the designer): U10 1(Int!/O16); U11 1(Int!/O16); U12 1(Int!/O16); U13 1(Int!/O16)

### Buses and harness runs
bus B[129..144] = port B[129..144]
bus B[145..160] = port B[145..160]
bus B[161..176] = port B[161..176]
bus B[177..192] = port B[177..192]

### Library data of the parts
C3 = Cap: as C1 on sheet Drivers 1
U10-U13 = LED DRIVER

## Sheet Drivers 4.SchDoc: LED Driver Connections #4
size A; DocumentNumber: 1; SheetNumber: 11
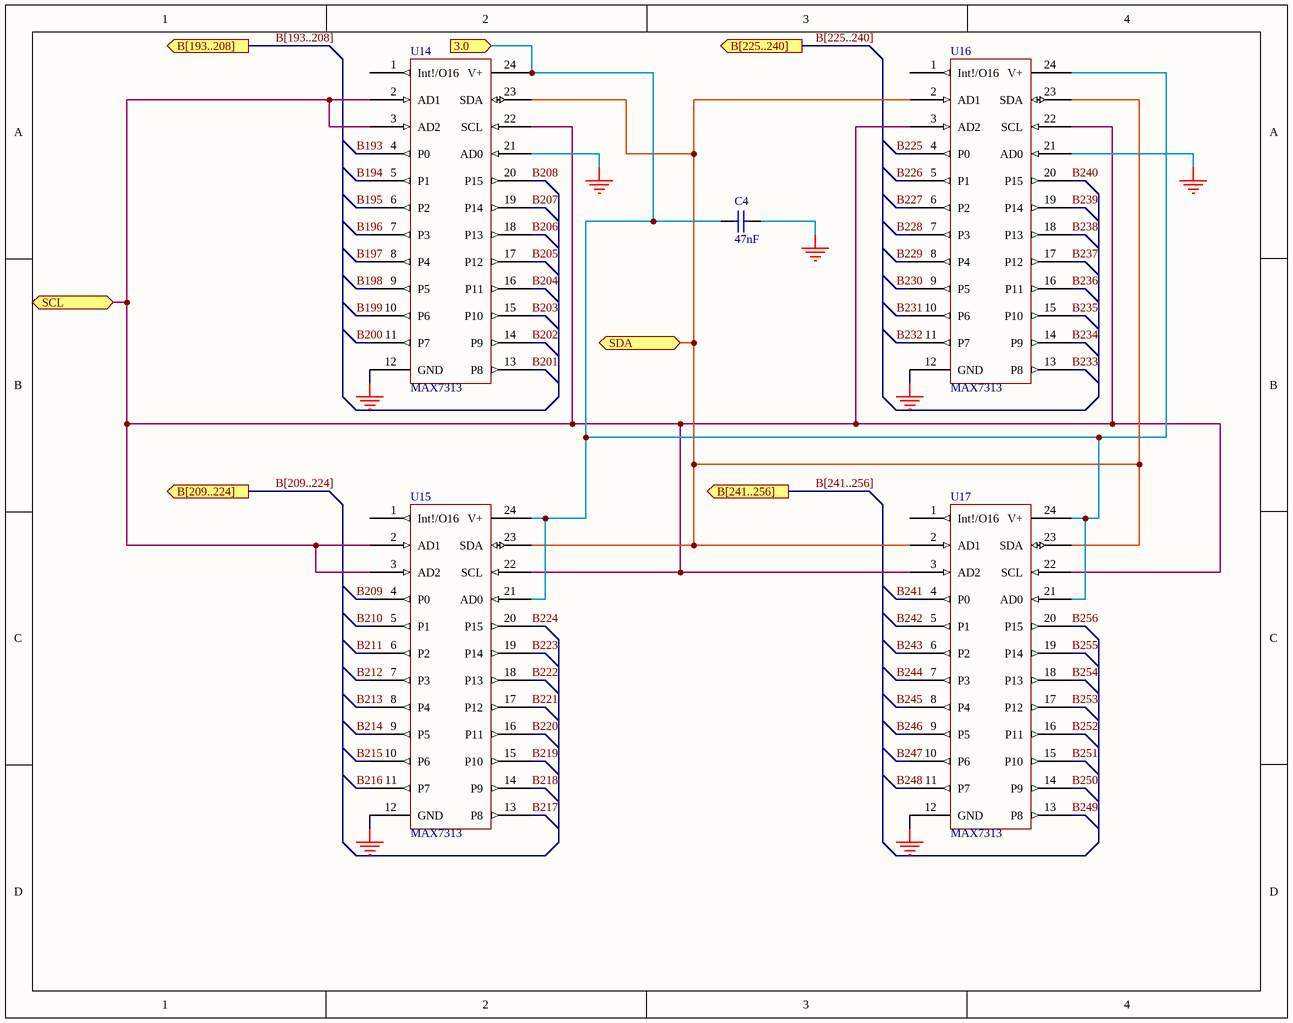
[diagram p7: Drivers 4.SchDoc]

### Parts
C4  47nF  [LED]
U14  MAX7313  [SSO-G24/C6.8]
U15  MAX7313  [SSO-G24/C6.8]
U16  MAX7313  [SSO-G24/C6.8]
U17  MAX7313  [SSO-G24/C6.8]

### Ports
3.0, B[193..208] (out), B[209..224] (out), B[225..240] (out), B[241..256] (out), SCL (bidir), SDA (bidir)

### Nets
GND: C4.2 U14.12(GND) U14.21(AD0) U15.12(GND) U16.12(GND) U16.21(AD0) U17.12(GND)
B193: U14.4(P0)
B194: U14.5(P1)
B195: U14.6(P2)
B196: U14.7(P3)
B197: U14.8(P4)
B198: U14.9(P5)
B199: U14.10(P6)
B200: U14.11(P7)
B201: U14.13(P8)
B202: U14.14(P9)
B203: U14.15(P10)
B204: U14.16(P11)
B205: U14.17(P12)
B206: U14.18(P13)
B207: U14.19(P14)
B208: U14.20(P15)
B209: U15.4(P0)
B210: U15.5(P1)
B211: U15.6(P2)
B212: U15.7(P3)
B213: U15.8(P4)
B214: U15.9(P5)
B215: U15.10(P6)
B216: U15.11(P7)
B217: U15.13(P8)
B218: U15.14(P9)
B219: U15.15(P10)
B220: U15.16(P11)
B221: U15.17(P12)
B222: U15.18(P13)
B223: U15.19(P14)
B224: U15.20(P15)
B225: U16.4(P0)
B226: U16.5(P1)
B227: U16.6(P2)
B228: U16.7(P3)
B229: U16.8(P4)
B230: U16.9(P5)
B231: U16.10(P6)
B232: U16.11(P7)
B233: U16.13(P8)
B234: U16.14(P9)
B235: U16.15(P10)
B236: U16.16(P11)
B237: U16.17(P12)
B238: U16.18(P13)
B239: U16.19(P14)
B240: U16.20(P15)
B241: U17.4(P0)
B242: U17.5(P1)
B243: U17.6(P2)
B244: U17.7(P3)
B245: U17.8(P4)
B246: U17.9(P5)
B247: U17.10(P6)
B248: U17.11(P7)
B249: U17.13(P8)
B250: U17.14(P9)
B251: U17.15(P10)
B252: U17.16(P11)
B253: U17.17(P12)
B254: U17.18(P13)
B255: U17.19(P14)
B256: U17.20(P15)
NetC1_1: C4.1 U14.24(V+) U15.21(AD0) U15.24(V+) U16.24(V+) U17.21(AD0) U17.24(V+) ; port 3.0
NetR33_1: U14.23(SDA) U15.23(SDA) U16.2(AD1) U16.23(SDA) U17.2(AD1) U17.23(SDA) ; port SDA
NetR34_1: U14.2(AD1) U14.3(AD2) U14.22(SCL) U15.2(AD1) U15.3(AD2) U15.22(SCL) U16.3(AD2) U16.22(SCL) U17.3(AD2) U17.22(SCL) ; port SCL

Not connected (* = marked no-connect by the designer): U14 1(Int!/O16); U15 1(Int!/O16); U16 1(Int!/O16); U17 1(Int!/O16)

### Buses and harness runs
bus B[193..208] = port B[193..208]
bus B[209..224] = port B[209..224]
bus B[225..240] = port B[225..240]
bus B[241..256] = port B[241..256]

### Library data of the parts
C4 = Cap: as C1 on sheet Drivers 1
U14-U17 = LED DRIVER

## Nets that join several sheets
GND: Microprocessor (12 pins), Drivers 1 (11 pins), Drivers 2 (13 pins), Drivers 3 (11 pins), Drivers 4 (7 pins)
B1: Output Headers 1 (R1.16), Drivers 1 (U2.4)
B2: Output Headers 1 (R1.15), Drivers 1 (U2.5)
B3: Output Headers 1 (R1.14), Drivers 1 (U2.6)
B4: Output Headers 1 (R1.13), Drivers 1 (U2.7)
B5: Output Headers 1 (R1.12), Drivers 1 (U2.8)
B6: Output Headers 1 (R1.11), Drivers 1 (U2.9)
B7: Output Headers 1 (R1.10), Drivers 1 (U2.10)
B8: Output Headers 1 (R1.9), Drivers 1 (U2.11)
B9: Output Headers 1 (R2.16), Drivers 1 (U2.13)
B10: Output Headers 1 (R2.2), Drivers 1 (U2.14)
B11: Output Headers 1 (R2.3), Drivers 1 (U2.15)
B12: Output Headers 1 (R2.4), Drivers 1 (U2.16)
B13: Output Headers 1 (R2.5), Drivers 1 (U2.17)
B14: Output Headers 1 (R2.6), Drivers 1 (U2.18)
B15: Output Headers 1 (R2.7), Drivers 1 (U2.19)
B16: Output Headers 1 (R2.8), Drivers 1 (U2.20)
B17: Output Headers 1 (R3.16), Drivers 1 (U3.4)
B18: Output Headers 1 (R3.15), Drivers 1 (U3.5)
B19: Output Headers 1 (R3.14), Drivers 1 (U3.6)
B20: Output Headers 1 (R3.13), Drivers 1 (U3.7)
B21: Output Headers 1 (R3.12), Drivers 1 (U3.8)
B22: Output Headers 1 (R3.11), Drivers 1 (U3.9)
B23: Output Headers 1 (R3.10), Drivers 1 (U3.10)
B24: Output Headers 1 (R3.9), Drivers 1 (U3.11)
B25: Output Headers 1 (R4.16), Drivers 1 (U3.13)
B26: Output Headers 1 (R4.2), Drivers 1 (U3.14)
B27: Output Headers 1 (R4.3), Drivers 1 (U3.15)
B28: Output Headers 1 (R4.4), Drivers 1 (U3.16)
B29: Output Headers 1 (R4.5), Drivers 1 (U3.17)
B30: Output Headers 1 (R4.6), Drivers 1 (U3.18)
B31: Output Headers 1 (R4.7), Drivers 1 (U3.19)
B32: Output Headers 1 (R4.8), Drivers 1 (U3.20)
B33: Output Headers 1 (R5.16), Drivers 1 (U4.4)
B34: Output Headers 1 (R5.15), Drivers 1 (U4.5)
B35: Output Headers 1 (R5.14), Drivers 1 (U4.6)
B36: Output Headers 1 (R5.13), Drivers 1 (U4.7)
B37: Output Headers 1 (R5.12), Drivers 1 (U4.8)
B38: Output Headers 1 (R5.11), Drivers 1 (U4.9)
B39: Output Headers 1 (R5.10), Drivers 1 (U4.10)
B40: Output Headers 1 (R5.9), Drivers 1 (U4.11)
B41: Output Headers 1 (R6.16), Drivers 1 (U4.13)
B42: Output Headers 1 (R6.2), Drivers 1 (U4.14)
B43: Output Headers 1 (R6.3), Drivers 1 (U4.15)
B44: Output Headers 1 (R6.4), Drivers 1 (U4.16)
B45: Output Headers 1 (R6.5), Drivers 1 (U4.17)
B46: Output Headers 1 (R6.6), Drivers 1 (U4.18)
B47: Output Headers 1 (R6.7), Drivers 1 (U4.19)
B48: Output Headers 1 (R6.8), Drivers 1 (U4.20)
B49: Output Headers 1 (R7.16), Drivers 1 (U5.4)
B50: Output Headers 1 (R7.15), Drivers 1 (U5.5)
B51: Output Headers 1 (R7.14), Drivers 1 (U5.6)
B52: Output Headers 1 (R7.13), Drivers 1 (U5.7)
B53: Output Headers 1 (R7.12), Drivers 1 (U5.8)
B54: Output Headers 1 (R7.11), Drivers 1 (U5.9)
B55: Output Headers 1 (R7.10), Drivers 1 (U5.10)
B56: Output Headers 1 (R7.9), Drivers 1 (U5.11)
B57: Output Headers 1 (R8.16), Drivers 1 (U5.13)
B58: Output Headers 1 (R8.2), Drivers 1 (U5.14)
B59: Output Headers 1 (R8.3), Drivers 1 (U5.15)
B60: Output Headers 1 (R8.4), Drivers 1 (U5.16)
B61: Output Headers 1 (R8.5), Drivers 1 (U5.17)
B62: Output Headers 1 (R8.6), Drivers 1 (U5.18)
B63: Output Headers 1 (R8.7), Drivers 1 (U5.19)
B64: Output Headers 1 (R8.8), Drivers 1 (U5.20)
B65: Output Headers 1 (R9.16), Drivers 2 (U6.4)
B66: Output Headers 1 (R9.15), Drivers 2 (U6.5)
B67: Output Headers 1 (R9.14), Drivers 2 (U6.6)
B68: Output Headers 1 (R9.13), Drivers 2 (U6.7)
B69: Output Headers 1 (R9.12), Drivers 2 (U6.8)
B70: Output Headers 1 (R9.11), Drivers 2 (U6.9)
B71: Output Headers 1 (R9.10), Drivers 2 (U6.10)
B72: Output Headers 1 (R9.9), Drivers 2 (U6.11)
B73: Output Headers 1 (R10.16), Drivers 2 (U6.13)
B74: Output Headers 1 (R10.2), Drivers 2 (U6.14)
B75: Output Headers 1 (R10.3), Drivers 2 (U6.15)
B76: Output Headers 1 (R10.4), Drivers 2 (U6.16)
B77: Output Headers 1 (R10.5), Drivers 2 (U6.17)
B78: Output Headers 1 (R10.6), Drivers 2 (U6.18)
B79: Output Headers 1 (R10.7), Drivers 2 (U6.19)
B80: Output Headers 1 (R10.8), Drivers 2 (U6.20)
B81: Output Headers 1 (R11.16), Drivers 2 (U7.4)
B82: Output Headers 1 (R11.15), Drivers 2 (U7.5)
B83: Output Headers 1 (R11.14), Drivers 2 (U7.6)
B84: Output Headers 1 (R11.13), Drivers 2 (U7.7)
B85: Output Headers 1 (R11.12), Drivers 2 (U7.8)
B86: Output Headers 1 (R11.11), Drivers 2 (U7.9)
B87: Output Headers 1 (R11.10), Drivers 2 (U7.10)
B88: Output Headers 1 (R11.9), Drivers 2 (U7.11)
B89: Output Headers 1 (R12.16), Drivers 2 (U7.13)
B90: Output Headers 1 (R12.2), Drivers 2 (U7.14)
B91: Output Headers 1 (R12.3), Drivers 2 (U7.15)
B92: Output Headers 1 (R12.4), Drivers 2 (U7.16)
B93: Output Headers 1 (R12.5), Drivers 2 (U7.17)
B94: Output Headers 1 (R12.6), Drivers 2 (U7.18)
B95: Output Headers 1 (R12.7), Drivers 2 (U7.19)
B96: Output Headers 1 (R12.8), Drivers 2 (U7.20)
B97: Output Headers 1 (R13.16), Drivers 2 (U8.4)
B98: Output Headers 1 (R13.15), Drivers 2 (U8.5)
B99: Output Headers 1 (R13.14), Drivers 2 (U8.6)
B100: Output Headers 1 (R13.13), Drivers 2 (U8.7)
B101: Output Headers 1 (R13.12), Drivers 2 (U8.8)
B102: Output Headers 1 (R13.11), Drivers 2 (U8.9)
B103: Output Headers 1 (R13.10), Drivers 2 (U8.10)
B104: Output Headers 1 (R13.9), Drivers 2 (U8.11)
B105: Output Headers 1 (R14.16), Drivers 2 (U8.13)
B106: Output Headers 1 (R14.2), Drivers 2 (U8.14)
B107: Output Headers 1 (R14.3), Drivers 2 (U8.15)
B108: Output Headers 1 (R14.4), Drivers 2 (U8.16)
B109: Output Headers 1 (R14.5), Drivers 2 (U8.17)
B110: Output Headers 1 (R14.6), Drivers 2 (U8.18)
B111: Output Headers 1 (R14.7), Drivers 2 (U8.19)
B112: Output Headers 1 (R14.8), Drivers 2 (U8.20)
B113: Output Headers 1 (R15.16), Drivers 2 (U9.4)
B114: Output Headers 1 (R15.15), Drivers 2 (U9.5)
B115: Output Headers 1 (R15.14), Drivers 2 (U9.6)
B116: Output Headers 1 (R15.13), Drivers 2 (U9.7)
B117: Output Headers 1 (R15.12), Drivers 2 (U9.8)
B118: Output Headers 1 (R15.11), Drivers 2 (U9.9)
B119: Output Headers 1 (R15.10), Drivers 2 (U9.10)
B120: Output Headers 1 (R15.9), Drivers 2 (U9.11)
B121: Output Headers 1 (R16.16), Drivers 2 (U9.13)
B122: Output Headers 1 (R16.2), Drivers 2 (U9.14)
B123: Output Headers 1 (R16.3), Drivers 2 (U9.15)
B124: Output Headers 1 (R16.4), Drivers 2 (U9.16)
B125: Output Headers 1 (R16.5), Drivers 2 (U9.17)
B126: Output Headers 1 (R16.6), Drivers 2 (U9.18)
B127: Output Headers 1 (R16.7), Drivers 2 (U9.19)
B128: Output Headers 1 (R16.8), Drivers 2 (U9.20)
B129: Output Headers 1 (R17.16), Drivers 3 (U10.4)
B130: Output Headers 1 (R17.15), Drivers 3 (U10.5)
B131: Output Headers 1 (R17.14), Drivers 3 (U10.6)
B132: Output Headers 1 (R17.13), Drivers 3 (U10.7)
B133: Output Headers 1 (R17.12), Drivers 3 (U10.8)
B134: Output Headers 1 (R17.11), Drivers 3 (U10.9)
B135: Output Headers 1 (R17.10), Drivers 3 (U10.10)
B136: Output Headers 1 (R17.9), Drivers 3 (U10.11)
B137: Output Headers 1 (R18.16), Drivers 3 (U10.13)
B138: Output Headers 1 (R18.2), Drivers 3 (U10.14)
B139: Output Headers 1 (R18.3), Drivers 3 (U10.15)
B140: Output Headers 1 (R18.4), Drivers 3 (U10.16)
B141: Output Headers 1 (R18.5), Drivers 3 (U10.17)
B142: Output Headers 1 (R18.6), Drivers 3 (U10.18)
B143: Output Headers 1 (R18.7), Drivers 3 (U10.19)
B144: Output Headers 1 (R18.8), Drivers 3 (U10.20)
B145: Output Headers 2 (R19.16), Drivers 3 (U11.4)
B146: Output Headers 2 (R19.15), Drivers 3 (U11.5)
B147: Output Headers 2 (R19.14), Drivers 3 (U11.6)
B148: Output Headers 2 (R19.13), Drivers 3 (U11.7)
B149: Output Headers 2 (R19.12), Drivers 3 (U11.8)
B150: Output Headers 2 (R19.11), Drivers 3 (U11.9)
B151: Output Headers 2 (R19.10), Drivers 3 (U11.10)
B152: Output Headers 2 (R19.9), Drivers 3 (U11.11)
B153: Output Headers 2 (R20.16), Drivers 3 (U11.13)
B154: Output Headers 2 (R20.2), Drivers 3 (U11.14)
B155: Output Headers 2 (R20.3), Drivers 3 (U11.15)
B156: Output Headers 2 (R20.4), Drivers 3 (U11.16)
B157: Output Headers 2 (R20.5), Drivers 3 (U11.17)
B158: Output Headers 2 (R20.6), Drivers 3 (U11.18)
B159: Output Headers 2 (R20.7), Drivers 3 (U11.19)
B160: Output Headers 2 (R20.8), Drivers 3 (U11.20)
B161: Output Headers 2 (R21.16), Drivers 3 (U12.4)
B162: Output Headers 2 (R21.15), Drivers 3 (U12.5)
B163: Output Headers 2 (R21.14), Drivers 3 (U12.6)
B164: Output Headers 2 (R21.13), Drivers 3 (U12.7)
B165: Output Headers 2 (R21.12), Drivers 3 (U12.8)
B166: Output Headers 2 (R21.11), Drivers 3 (U12.9)
B167: Output Headers 2 (R21.10), Drivers 3 (U12.10)
B168: Output Headers 2 (R21.9), Drivers 3 (U12.11)
B169: Output Headers 2 (R22.16), Drivers 3 (U12.13)
B170: Output Headers 2 (R22.2), Drivers 3 (U12.14)
B171: Output Headers 2 (R22.3), Drivers 3 (U12.15)
B172: Output Headers 2 (R22.4), Drivers 3 (U12.16)
B173: Output Headers 2 (R22.5), Drivers 3 (U12.17)
B174: Output Headers 2 (R22.6), Drivers 3 (U12.18)
B175: Output Headers 2 (R22.7), Drivers 3 (U12.19)
B176: Output Headers 2 (R22.8), Drivers 3 (U12.20)
B177: Output Headers 2 (R23.16), Drivers 3 (U13.4)
B178: Output Headers 2 (R23.15), Drivers 3 (U13.5)
B179: Output Headers 2 (R23.14), Drivers 3 (U13.6)
B180: Output Headers 2 (R23.13), Drivers 3 (U13.7)
B181: Output Headers 2 (R23.12), Drivers 3 (U13.8)
B182: Output Headers 2 (R23.11), Drivers 3 (U13.9)
B183: Output Headers 2 (R23.10), Drivers 3 (U13.10)
B184: Output Headers 2 (R23.9), Drivers 3 (U13.11)
B185: Output Headers 2 (R24.16), Drivers 3 (U13.13)
B186: Output Headers 2 (R24.2), Drivers 3 (U13.14)
B187: Output Headers 2 (R24.3), Drivers 3 (U13.15)
B188: Output Headers 2 (R24.4), Drivers 3 (U13.16)
B189: Output Headers 2 (R24.5), Drivers 3 (U13.17)
B190: Output Headers 2 (R24.6), Drivers 3 (U13.18)
B191: Output Headers 2 (R24.7), Drivers 3 (U13.19)
B192: Output Headers 2 (R24.8), Drivers 3 (U13.20)
B193: Output Headers 2 (R25.16), Drivers 4 (U14.4)
B194: Output Headers 2 (R25.15), Drivers 4 (U14.5)
B195: Output Headers 2 (R25.14), Drivers 4 (U14.6)
B196: Output Headers 2 (R25.13), Drivers 4 (U14.7)
B197: Output Headers 2 (R25.12), Drivers 4 (U14.8)
B198: Output Headers 2 (R25.11), Drivers 4 (U14.9)
B199: Output Headers 2 (R25.10), Drivers 4 (U14.10)
B200: Output Headers 2 (R25.9), Drivers 4 (U14.11)
B201: Output Headers 2 (R26.16), Drivers 4 (U14.13)
B202: Output Headers 2 (R26.2), Drivers 4 (U14.14)
B203: Output Headers 2 (R26.3), Drivers 4 (U14.15)
B204: Output Headers 2 (R26.4), Drivers 4 (U14.16)
B205: Output Headers 2 (R26.5), Drivers 4 (U14.17)
B206: Output Headers 2 (R26.6), Drivers 4 (U14.18)
B207: Output Headers 2 (R26.7), Drivers 4 (U14.19)
B208: Output Headers 2 (R26.8), Drivers 4 (U14.20)
B209: Output Headers 2 (R27.16), Drivers 4 (U15.4)
B210: Output Headers 2 (R27.15), Drivers 4 (U15.5)
B211: Output Headers 2 (R27.14), Drivers 4 (U15.6)
B212: Output Headers 2 (R27.13), Drivers 4 (U15.7)
B213: Output Headers 2 (R27.12), Drivers 4 (U15.8)
B214: Output Headers 2 (R27.11), Drivers 4 (U15.9)
B215: Output Headers 2 (R27.10), Drivers 4 (U15.10)
B216: Output Headers 2 (R27.9), Drivers 4 (U15.11)
B217: Output Headers 2 (R28.16), Drivers 4 (U15.13)
B218: Output Headers 2 (R28.2), Drivers 4 (U15.14)
B219: Output Headers 2 (R28.3), Drivers 4 (U15.15)
B220: Output Headers 2 (R28.4), Drivers 4 (U15.16)
B221: Output Headers 2 (R28.5), Drivers 4 (U15.17)
B222: Output Headers 2 (R28.6), Drivers 4 (U15.18)
B223: Output Headers 2 (R28.7), Drivers 4 (U15.19)
B224: Output Headers 2 (R28.8), Drivers 4 (U15.20)
B225: Output Headers 2 (R29.16), Drivers 4 (U16.4)
B226: Output Headers 2 (R29.15), Drivers 4 (U16.5)
B227: Output Headers 2 (R29.14), Drivers 4 (U16.6)
B228: Output Headers 2 (R29.13), Drivers 4 (U16.7)
B229: Output Headers 2 (R29.12), Drivers 4 (U16.8)
B230: Output Headers 2 (R29.11), Drivers 4 (U16.9)
B231: Output Headers 2 (R29.10), Drivers 4 (U16.10)
B232: Output Headers 2 (R29.9), Drivers 4 (U16.11)
B233: Output Headers 2 (R30.16), Drivers 4 (U16.13)
B234: Output Headers 2 (R30.2), Drivers 4 (U16.14)
B235: Output Headers 2 (R30.3), Drivers 4 (U16.15)
B236: Output Headers 2 (R30.4), Drivers 4 (U16.16)
B237: Output Headers 2 (R30.5), Drivers 4 (U16.17)
B238: Output Headers 2 (R30.6), Drivers 4 (U16.18)
B239: Output Headers 2 (R30.7), Drivers 4 (U16.19)
B240: Output Headers 2 (R30.8), Drivers 4 (U16.20)
B241: Output Headers 2 (R31.16), Drivers 4 (U17.4)
B242: Output Headers 2 (R31.15), Drivers 4 (U17.5)
B243: Output Headers 2 (R31.14), Drivers 4 (U17.6)
B244: Output Headers 2 (R31.13), Drivers 4 (U17.7)
B245: Output Headers 2 (R31.12), Drivers 4 (U17.8)
B246: Output Headers 2 (R31.11), Drivers 4 (U17.9)
B247: Output Headers 2 (R31.10), Drivers 4 (U17.10)
B248: Output Headers 2 (R31.9), Drivers 4 (U17.11)
B249: Output Headers 2 (R32.16), Drivers 4 (U17.13)
B250: Output Headers 2 (R32.2), Drivers 4 (U17.14)
B251: Output Headers 2 (R32.3), Drivers 4 (U17.15)
B252: Output Headers 2 (R32.4), Drivers 4 (U17.16)
B253: Output Headers 2 (R32.5), Drivers 4 (U17.17)
B254: Output Headers 2 (R32.6), Drivers 4 (U17.18)
B255: Output Headers 2 (R32.7), Drivers 4 (U17.19)
B256: Output Headers 2 (R32.8), Drivers 4 (U17.20)
NetC1_1: Microprocessor (R36.2 U18.2), Drivers 1 (7 pins), Drivers 2 (9 pins), Drivers 3 (7 pins), Drivers 4 (7 pins)
NetR33_1: Microprocessor (R33.1 U1.23), Drivers 1 (6 pins), Drivers 2 (U6.23 U7.23 U8.23 U9.23), Drivers 3 (6 pins), Drivers 4 (6 pins)
NetR34_1: Microprocessor (R34.1 U1.22), Drivers 1 (6 pins), Drivers 2 (U6.22 U7.22 U8.22 U9.22), Drivers 3 (6 pins), Drivers 4 (10 pins)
